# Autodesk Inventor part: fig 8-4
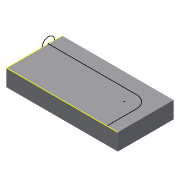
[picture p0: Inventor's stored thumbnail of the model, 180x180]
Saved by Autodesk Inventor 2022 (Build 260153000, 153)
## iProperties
Created: 2009-04
Part Number: fig 8-4
Document SubType Name: Modeling
Designer: Sham
Density: 1 g/cm^3
Material: Generic
Appearance: Default
Author: Sham
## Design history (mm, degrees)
sketch "Sketch1"
  geometry: L1 (-20, 20)-(20, 20); L2 (20, 20)-(20, 0); L3 (20, 0)-(-20, 0); L4 (-20, 0)-(-20, 20)
  constraints: 8 end point
extrude "Extrusion1" new body sketch "Sketch1" distance "d0" = 6; taper "d1" = 0 deg
sketch "Sketch4"
  geometry: L1 (6, 0)-(6, 20) reference; C1 r 2.236 at (6, 15)
  constraints: 1 centre point, 1 point on line
sketch "Sketch5"
  geometry: L1 (-20, 0)-(-20, 20) reference; L2 (20, 0)-(-20, 0) reference; L3 (-20, 15)-(11.667, 15); L4 (16, 10.667)-(16, 0); A1 r 4.333 centre (11.667, 10.667) between (16, 10.667) and (11.667, 15)
  constraints: 4 end point, 2 point on circle, 2 point on line, 1 centre point, 1 tangent
body "Solid1"
